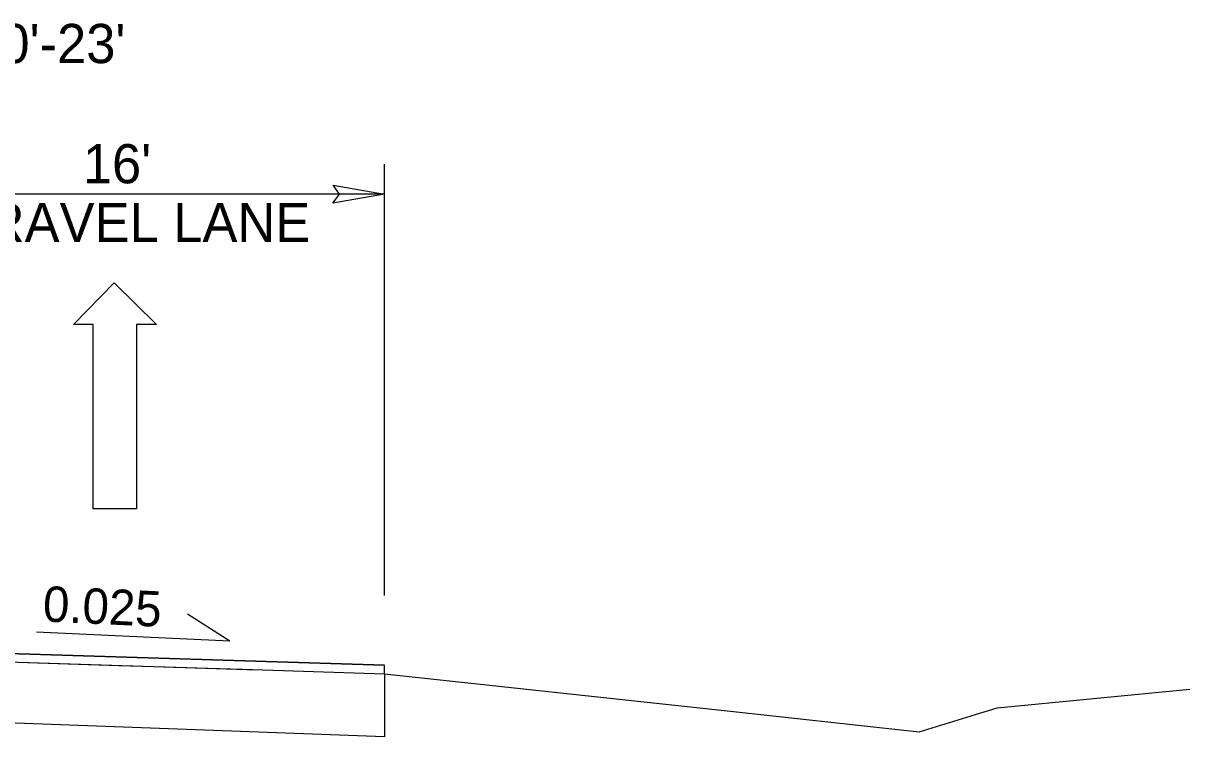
# Model space of a CAD drawing. Extents: x 2176156 to 2177167, y 76401 to 76644.
# Drawn here: x 2176849.74 to 2176884.04, y 76415.1 to 76436.09 of the extents above; entities that cross this region are included whole.
import ezdxf

# ---------------------------------------------------------------- set-up
doc = ezdxf.new("R2010")
doc.units = 0
for name, color, linetype in [('Exist Roads Curbs', 7, 'Continuous'), ('Exist Structure Minor Culvert Topo', 7, 'Continuous'), ('Exist Structure Minor Drop Inlet', 7, 'Continuous'), ('Exist Utilities Other Pole CELL', 7, 'Continuous'), ('Old_Level_1', 7, 'Continuous'), ('Old_Level_3', 7, 'Continuous'), ('Sheet Plan CELL', 7, 'Continuous')]:
    doc.layers.add(name, color=color, linetype=linetype)

msp = doc.modelspace()

# ---------------------------------------------------------------- linework, layer by layer
at = {"layer": 'Exist Roads Curbs'}
for p, q in [((2176836.359, 76417.701), (2176856.626, 76417.069)), ((2176844.366, 76417.701), (2176860.366, 76417.202)), ((2176860.366, 76417.202), (2176844.366, 76417.701)), ((2176844.366, 76417.451), (2176852.548, 76417.196)), ((2176860.366, 76416.952), (2176860.366, 76417.202))]:
    msp.add_line(p, q, dxfattribs=at)
msp.add_lwpolyline([(2176852.548, 76417.196), (2176853.236, 76417.175), (2176854.234, 76417.144), (2176855.174, 76417.114), (2176856.193, 76417.082), (2176860.366, 76416.952)], dxfattribs=at)
at = {"layer": 'Exist Structure Minor Drop Inlet'}
for p, q in [((2176851.214, 76427.23), (2176852.416, 76428.452)), ((2176852.416, 76428.452), (2176853.658, 76427.23)), ((2176851.796, 76427.23), (2176851.214, 76427.23)), ((2176851.796, 76421.798), (2176851.796, 76427.23)), ((2176853.658, 76427.23), (2176853.076, 76427.23)), ((2176853.076, 76427.23), (2176853.076, 76421.798)), ((2176853.076, 76421.798), (2176851.796, 76421.798))]:
    msp.add_line(p, q, dxfattribs=at)
at = {"layer": 'Exist Utilities Other Pole CELL'}
for q in [(2176854.574, 76418.708), (2176850.135, 76418.177)]:
    msp.add_line((2176855.814, 76417.912), q, dxfattribs=at)
at = {"layer": 'Old_Level_1'}
msp.add_lwpolyline([(2176858.857, 76431.325), (2176860.366, 76431.065), (2176858.848, 76430.796), (2176859.041, 76431.065)], close=True, dxfattribs=at)
at = {"layer": 'Old_Level_3'}
for p, q in [((2176860.366, 76419.252), (2176860.366, 76431.949)), ((2176860.366, 76431.065), (2176844.366, 76431.065))]:
    msp.add_line(p, q, dxfattribs=at)
at = {"layer": 'Sheet Plan CELL'}
for p, q in [((2176860.366, 76416.952), (2176860.366, 76415.098)), ((2176860.366, 76415.098), (2176835.691, 76415.992))]:
    msp.add_line(p, q, dxfattribs=at)
msp.add_lwpolyline([(2176860.366, 76416.952), (2176870.175, 76415.887), (2176876.086, 76415.244), (2176878.386, 76415.947), (2176884.043, 76416.495)], dxfattribs=at)

# ---------------------------------------------------------------- texts
at = {"layer": 'Exist Structure Minor Culvert Topo'}
for s, height, p in [("VARIES 0'-23'", 1.15334, (2176842.984, 76434.918)), ("16'", 1.1533, (2176851.494, 76431.381)), ('TRAVEL LANE', 1.15334, (2176847.725, 76429.651))]:
    msp.add_text(s, height=height, dxfattribs=at).set_placement(p)
at = {"layer": 'Exist Utilities Other Pole CELL'}
msp.add_text('0.025', height=1.0429, rotation=357.3324, dxfattribs=at).set_placement((2176850.301, 76418.491))

doc.saveas('drawing.dxf')
